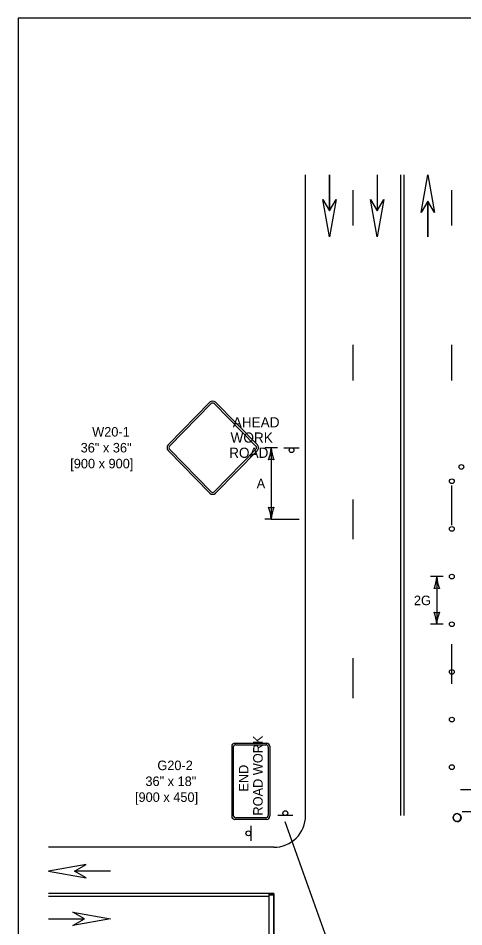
# Model space of a CAD drawing. Extents: x 49991.4 to 50021, y 49987.6 to 50011.4.
# Drawn here: x 50000.34 to 50003.14, y 50005.54 to 50011.26 of the extents above; entities that cross this region are included whole.
import ezdxf

# ---------------------------------------------------------------- set-up
doc = ezdxf.new("R2010")
doc.units = 0
for name, color, linetype in [('Level 1', 7, 'Continuous'), ('Level 2', 7, 'Continuous'), ('Level 3', 7, 'Continuous')]:
    doc.layers.add(name, color=color, linetype=linetype)

msp = doc.modelspace()

# ---------------------------------------------------------------- linework, layer by layer
at = {"layer": 'Level 1'}
for p, q in [((50002.1435, 50006.2426), (50002.1435, 50010.2756)), ((50002.2931, 50010.2756), (50002.2931, 50010.0497)), ((50002.2935, 50010.2756), (50002.2935, 50010.0497)), ((50002.5931, 50010.2756), (50002.5931, 50010.0497)), ((50002.5935, 50010.2756), (50002.5935, 50010.0497)), ((50002.7435, 50006.2426), (50002.7435, 50010.2756)), ((50002.7635, 50006.2426), (50002.7635, 50010.2756)), ((50002.4436, 50009.9566), (50002.4436, 50010.1806)), ((50003.0636, 50009.9566), (50003.0636, 50010.1806)), ((50002.9135, 50009.8855), (50002.9135, 50010.1114)), ((50002.9139, 50009.8855), (50002.9139, 50010.1114)), ((50002.4436, 50008.9826), (50002.4436, 50009.2066)), ((50003.0636, 50008.9826), (50003.0636, 50009.2066)), ((50001.2792, 50008.5765), (50001.5417, 50008.8445)), ((50001.2879, 50008.5679), (50001.5505, 50008.8359)), ((50001.5689, 50008.8359), (50001.8314, 50008.5679)), ((50001.5776, 50008.8445), (50001.8402, 50008.5765)), ((50001.5417, 50008.2726), (50001.2792, 50008.5406)), ((50001.5505, 50008.2812), (50001.2879, 50008.5492)), ((50001.8314, 50008.5492), (50001.5689, 50008.2812)), ((50001.8402, 50008.5406), (50001.5776, 50008.2726)), ((50002.0075, 50008.5586), (50002.1035, 50008.5586)), ((50003.0636, 50008.071), (50003.0636, 50008.321)), ((50002.4436, 50007.9826), (50002.4436, 50008.2326)), ((50003.0636, 50007.071), (50003.0636, 50007.321)), ((50002.4436, 50006.9826), (50002.4436, 50007.2326)), ((50001.6991, 50006.6986), (50001.8991, 50006.6986)), ((50001.7041, 50006.6886), (50001.8941, 50006.6886)), ((50001.6791, 50006.6786), (50001.6791, 50006.2386)), ((50001.6891, 50006.6736), (50001.6891, 50006.2436)), ((50001.9091, 50006.6736), (50001.9091, 50006.2436)), ((50001.9192, 50006.6785), (50001.9192, 50006.2385)), ((50003.2141, 50006.405), (50003.1181, 50006.405)), ((50001.8941, 50006.2286), (50001.7041, 50006.2286)), ((50002.0641, 50006.2426), (50001.9681, 50006.2426)), ((50003.1288, 50006.2684), (50003.2248, 50006.2684)), ((50001.8991, 50006.2186), (50001.6991, 50006.2186)), ((50001.7991, 50006.1786), (50001.7991, 50006.0826)), ((50001.9435, 50006.0426), (50000.5266, 50006.0426)), ((50000.9167, 50005.8927), (50000.6908, 50005.8927)), ((50000.9167, 50005.8923), (50000.6908, 50005.8923)), ((50001.9435, 50005.7527), (50000.5266, 50005.7527)), ((50001.9135, 50005.7327), (50000.5266, 50005.7327)), ((50001.9135, 50005.7527), (50001.9135, 50005.4426)), ((50001.9135, 50005.7427), (50001.9435, 50005.7427)), ((50001.9435, 50005.7527), (50001.9435, 50005.4426)), ((50000.5266, 50005.5927), (50000.7525, 50005.5927)), ((50000.5266, 50005.5923), (50000.7525, 50005.5923))]:
    msp.add_line(p, q, dxfattribs=at)
for points in [[(50008.6146, 50011.2628), (50000.3356, 50011.2628), (50000.3356, 50000.0624), (50008.6146, 50000.0624)], [(50002.8719, 50010.0391), (50002.9135, 50010.2756), (50002.9555, 50010.0391), (50002.9135, 50010.1113)], [(50002.3351, 50010.122), (50002.2935, 50009.8855), (50002.2515, 50010.122), (50002.2935, 50010.0498)], [(50002.6351, 50010.122), (50002.5935, 50009.8855), (50002.5515, 50010.122), (50002.5935, 50010.0498)], [(50000.7631, 50005.9343), (50000.5266, 50005.8927), (50000.7631, 50005.8507), (50000.6909, 50005.8927)], [(50000.6802, 50005.6343), (50000.9167, 50005.5927), (50000.6802, 50005.5507), (50000.7524, 50005.5927)]]:
    msp.add_lwpolyline(points, close=True, dxfattribs=at)
for points in [[(50001.9435, 50005.7427), (50001.9435, 50005.7527), (50001.9135, 50005.7527), (50001.9135, 50005.7427), (50001.9435, 50005.7427)], [(50001.9135, 50005.4426), (50001.9435, 50005.4426), (50001.9435, 50005.7427), (50001.9135, 50005.7427), (50001.9135, 50005.4426)]]:
    msp.add_lwpolyline(points, dxfattribs=at)
for centre, radius in [((50002.0555, 50008.5434), 0.0152), ((50003.1238, 50008.4373), 0.015), ((50003.0638, 50008.3472), 0.015), ((50003.0638, 50008.0472), 0.015), ((50003.0638, 50007.7472), 0.015), ((50003.0638, 50007.4472), 0.015), ((50003.0638, 50007.1472), 0.015), ((50003.0638, 50006.8472), 0.015), ((50003.0638, 50006.5472), 0.015), ((50002.0161, 50006.2578), 0.0152), ((50003.0965, 50006.2297), 0.025), ((50001.784, 50006.1306), 0.0152)]:
    msp.add_circle(centre, radius, dxfattribs=at)
for centre, radius, start, end in [((50001.6991, 50006.6786), 0.02, 90, 180), ((50001.7041, 50006.6736), 0.015, 90, 180), ((50001.8941, 50006.6736), 0.015, 360, 90), ((50001.8991, 50006.6785), 0.02, 360, 90), ((50001.6991, 50006.2386), 0.02, 180, 270), ((50001.7041, 50006.2436), 0.015, 180, 270), ((50001.8941, 50006.2436), 0.015, 270, 360), ((50001.8991, 50006.2385), 0.02, 270, 360), ((50001.9435, 50006.2426), 0.2, 270, 0.0007), ((50003.0965, 50006.2297), 0.025, 357.0759, 177.0759), ((50003.0965, 50006.2297), 0.025, 177.0759, 357.0759)]:
    msp.add_arc(centre, radius, start, end, dxfattribs=at)
for centre, major_axis, ratio, start_param, end_param in [((50001.5597, 50008.8265), (0, 0.0255), 0.98963, 5.497795, 7.068583), ((50001.5597, 50008.8265), (0, 0.0132), 0.98, 5.497795, 7.068583), ((50001.2971, 50008.5586), (0, -0.0255), 0.98963, 3.926991, 5.497787), ((50001.2971, 50008.5586), (0, -0.0132), 0.98, 3.926991, 5.497787), ((50001.8222, 50008.5586), (0, -0.0132), 0.98, 0.785394, 2.356194), ((50001.8222, 50008.5586), (0, -0.0255), 0.98963, 0.785394, 2.356194), ((50001.5597, 50008.2907), (0, -0.0132), 0.98, 5.497787, 7.068583), ((50001.5597, 50008.2907), (0, -0.0255), 0.98963, 5.497787, 7.068583)]:
    msp.add_ellipse(centre, major_axis=major_axis, ratio=ratio, start_param=start_param, end_param=end_param, dxfattribs=at)
at = {"layer": 'Level 3'}
for p, q in [((50001.9675, 50008.5586), (50001.8875, 50008.5586)), ((50001.9275, 50008.5586), (50001.9275, 50008.1086)), ((50001.9275, 50008.1086), (50001.8875, 50008.1086)), ((50001.9275, 50008.1086), (50002.1035, 50008.1086)), ((50003.0088, 50007.7472), (50002.9288, 50007.7472)), ((50002.9688, 50007.7472), (50002.9688, 50007.4472)), ((50003.0088, 50007.4472), (50002.9288, 50007.4472)), ((50002.5561, 50004.6926), (50002.0161, 50006.2026))]:
    msp.add_line(p, q, dxfattribs=at)
for centre, radius, start, end in [((50001.7053, 50008.5678), 0.2223, 337.456, 357.6395), ((50002.1602, 50008.5701), 0.233, 182.8273, 202.0772), ((50001.9275, 50008.4304), 0.0548, 72.1388, 107.8612), ((50001.9275, 50008.2368), 0.0548, 252.1388, 287.8612), ((50001.6948, 50008.0971), 0.233, 2.8273, 22.0772), ((50002.1496, 50008.0994), 0.2223, 157.456, 177.6395), ((50002.7467, 50007.7564), 0.2223, 337.456, 357.6395), ((50003.2015, 50007.7587), 0.233, 182.8273, 202.0772), ((50002.9688, 50007.619), 0.0548, 72.1388, 107.8612), ((50002.9688, 50007.5755), 0.0548, 252.1388, 287.8612), ((50002.7361, 50007.4357), 0.233, 2.8273, 22.0772), ((50003.1909, 50007.4381), 0.2223, 157.456, 177.6395)]:
    msp.add_arc(centre, radius, start, end, dxfattribs=at)

# ---------------------------------------------------------------- texts
at = {"layer": 'Level 1'}
for s, height, rotation, p in [('AHEAD', 0.06389, 360, (50001.6854, 50008.6863)), ('WORK', 0.06389, 360, (50001.6718, 50008.5905)), ('ROAD', 0.06389, 360, (50001.6628, 50008.4947)), ('ROAD WORK', 0.06, 90, (50001.8738, 50006.2427)), ('END', 0.06, 90, (50001.7838, 50006.3934))]:
    msp.add_text(s, height=height, rotation=rotation, dxfattribs=at).set_placement(p)
at = {"layer": 'Level 2'}
for s, p in [('W20-1', (50000.801, 50008.6286)), ('36" x 36"', (50000.7287, 50008.5286)), ('[900 x 900]', (50000.6631, 50008.4286)), ('A', (50001.836, 50008.3036))]:
    msp.add_text(s, height=0.06, rotation=360, dxfattribs=at).set_placement(p)
for s, p in [('2G', (50002.8252, 50007.5672)), ('G20-2', (50001.2112, 50006.5286)), ('36" x 18"', (50001.136, 50006.4286)), ('[900 x 450]', (50001.0704, 50006.3286))]:
    msp.add_text(s, height=0.06, dxfattribs=at).set_placement(p)

doc.saveas('drawing.dxf')
